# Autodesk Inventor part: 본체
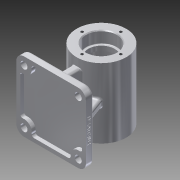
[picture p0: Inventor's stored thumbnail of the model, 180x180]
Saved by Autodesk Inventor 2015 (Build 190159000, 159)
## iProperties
Created: 2019-06
Part Number: 본체
Material: 알루미늄 6061
Document SubType Name: Modeling
Designer: a3
Density: 2.7 g/cm^3
Appearance: 알루미늄 - 평지
Mass: 610.032 g
Surface Area: 623.426 cm^2
Volume: 225.938 cm^3
Author: a3
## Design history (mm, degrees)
sketch "스케치2"
  geometry: L1 (45, 45)-(-45, 45); L2 (-45, 45)-(-45, -45); L3 (-45, -45)-(45, -45); L4 (45, -45)-(45, 45); L5 (45, 45)-(-45, -45); 2 further points
  constraints: 10 end point, 2 parallel, 1 coincident, 1 horizontal, 1 midpoint, 1 perpendicular
  dimensions: "d4" = 90 distance of L3.end L1.start; "d5" = 90 distance of L1.start L1.end
extrude "돌출2" new body sketch "스케치2" distance "d6" = 10; taper "d7" = 0 deg
sketch "스케치3"
  geometry: L1 (65, 40.611)-(65, -47.854); L2 (85, 45)-(85, 30); L3 (85, 30)-(82, 30); L4 (82, 30)-(82, 24); L5 (82, 24)-(90, 24); L6 (90, 24)-(90, -24); L7 (90, -24)-(82, -24); L8 (82, -24)-(82, -30); L9 (82, -30)-(85, -30); L10 (85, -30)-(85, -45); L11 (85, -45)-(97, -45); L12 (97, -45)-(97, 45); L13 (97, 45)-(85, 45); L14 (0, 45)-(0, -45) reference; 1 further point
  constraints: 26 end point, 10 perpendicular, 2 collinear, 2 vertical, 1 horizontal
  dimensions: "d8" = 65 distance between parallel lines of L1 L14; "d9" = 64 diameter of L12 L1; "d10" = 34 diameter of L4 L1; "d11" = 40 diameter of L2 L1; "d12" = 50 diameter of L6 L1; "d13" = 90 distance between parallel lines of L11 L13; "d14" = 45 distance from line of L11 point (0, 0); "d15" = 48 distance between parallel lines of L7 L5; "d16" = 15 distance from line of L3.end L13; "d17" = 15 distance from line of L11 L8.end; "d18" = 24 distance from line of L7 point (0, 0)
revolve "회전1" sketch "스케치3" stored, may be unused: angle "d19" = 90 deg
sketch "스케치4"
  geometry: L1 (-5, -35)-(5, -35); L2 (5, -35)-(5, 35); L3 (5, 35)-(-5, 35); L4 (-5, 35)-(-5, -35); L5 (-5, -35)-(5, 35); 2 further points
  constraints: 10 end point, 2 parallel, 1 coincident, 1 horizontal, 1 midpoint, 1 perpendicular
  dimensions: "d20" = 70 distance of L3.end L1.start; "d21" = 10 distance of L1.start L1.end
extrude "돌출3" join sketch "스케치4" stored distance "d22" = 10; taper "d23" = 0 deg
sketch "스케치5"
  geometry: L1 (0, 0)-(0, 40); L2 (-35, 10)-(-23.058, 42.811); 2 further points
  constraints: 4 end point, 1 vertical, 1 vertical alignment, 3 other
  dimensions: "d33" = 20 deg angle of L2 L1; "d34" = 14.07813 distance from line of point (0, 65) L2; "d35" = 35 distance from line of L2.start L1
feature "리브1" sketch "스케치5" dims "d27" = 1, "d28" = 10, "d29" = 0, "d30" = 0, "d31" = 1, "d32" = 1
fillet "모깎기1" dims "d40" = 10
sketch "스케치6"
  geometry: L1 (22.155, 40)-(-22.155, 40); L2 (-22.155, -40)-(22.155, -40); L3 (40, -22.155)-(40, 22.155); L4 (-40, -40)-(40, 40); L5 (-40, -22.155)-(-40, 22.155); A1 r 10 centre (-35, -35) between (-45, -35) and (-35, -45) reference; A2 r 10 centre (35, -35) between (35, -45) and (45, -35) reference; A3 r 10 centre (35, 35) between (45, 35) and (35, 45) reference; A4 r 10 centre (-35, 35) between (-35, 45) and (-45, 35) reference; A5 r 10 centre (-35, -35) between (-25.119, -36.538) and (-36.538, -25.119); A6 r 10 centre (-35, 35) between (-36.538, 25.119) and (-25.119, 36.538); A7 r 10 centre (35, 35) between (45, 35) and (35, 45) reference; A8 r 10 centre (35, 35) between (25.119, 36.538) and (36.538, 25.119); A9 r 10 centre (35, -35) between (36.538, -25.119) and (25.119, -36.538); A10 r 3 centre (-37, -22.155) between (-40, -22.155) and (-36.538, -25.119); A11 r 3 centre (-22.155, -37) between (-25.119, -36.538) and (-22.155, -40); A12 r 3 centre (22.155, -37) between (22.155, -40) and (25.119, -36.538); A13 r 3 centre (37, -22.155) between (36.538, -25.119) and (40, -22.155); A14 r 3 centre (37, 22.155) between (40, 22.155) and (36.538, 25.119); A15 r 3 centre (22.155, 37) between (25.119, 36.538) and (22.155, 40); A16 r 3 centre (-22.155, 37) between (-22.155, 40) and (-25.119, 36.538); A17 r 3 centre (-37, 22.155) between (-36.538, 25.119) and (-40, 22.155); 10 further points
  constraints: 32 point on circle, 16 tangent, 12 centre point, 10 end point, 8 point on line, 6 equal radius, 5 coincident, 2 parallel, 1 horizontal, 1 midpoint, 1 vertical
  dimensions: "d41" = 20 diameter of A8; "d42" = 20 diameter of A9; "d43" = 20 diameter of A6; "d44" = 20 diameter of A5; "d45" = 45 deg angle of L3 L4; "d47" = 80 distance between parallel lines of L1 L2; "d48" = 5 distance from line of A3.start L3; "d49" = 75 distance from line of A3.start L2; "d50" = 3 radius of A10; "d51" = 3 radius of A11; "d52" = 80 distance between parallel lines of L3 L5; "d53" = 0 distance from line of L4.end L3
extrude "돌출4" cut sketch "스케치6" distance "d54" = 5; taper "d55" = 0 deg
sketch "스케치7"
  geometry: L1 (35, 45)-(-35, 45) reference; L2 (-45, 35)-(-45, -35) reference; L3 (-35, -45)-(35, -45) reference; L4 (45, -35)-(45, 35) reference; L5 (-35, -5)-(-35, 5) reference; L6 (-35, 5)-(-5, 5) reference; L7 (-5, 5)-(-5, 35) reference; L8 (-5, 35)-(5, 35) reference; L9 (5, 35)-(5, 5) reference; L10 (5, 5)-(35, 5) reference; L11 (35, 5)-(35, -5) reference; L12 (35, -5)-(5, -5) reference; L13 (5, -5)-(5, -35) reference; L14 (5, -35)-(-5, -35) reference; L15 (-5, -35)-(-5, -5) reference; L16 (-5, -5)-(-35, -5) reference; A1 r 10 centre (35, 35) between (45, 35) and (35, 45) reference; A2 r 10 centre (-35, 35) between (-35, 45) and (-45, 35) reference; A3 r 10 centre (-35, -35) between (-45, -35) and (-35, -45) reference; A4 r 10 centre (35, -35) between (35, -45) and (45, -35) reference; 1 further point
hole "구멍1" sketch "스케치7" at (-35, 35), (-35, -35), (35, -35), (35, 35) diameter "d56" = 9; stored, may be unused: countersink angle "d60" = 90 deg, drill point angle "d62" = 118 deg; dims "d57" = 6, "d58" = 4, "d59" = 2, "d61" = 8
sketch "스케치8"
  geometry: L1 (0, 0)-(0, 25); C1 r 20 at (0, 0) reference; 1 further point
  constraints: 2 end point, 1 vertical
  dimensions: "d63" = 25 distance of L1.start L1.end
hole "구멍2" sketch "스케치8" at (0, 25) diameter "d64" = 3.459; stored, may be unused: countersink angle "d68" = 90 deg, drill point angle "d70" = 118 deg; dims "d65" = 7, "d66" = 4, "d67" = 2, "d69" = 9
node "작업 평면1"
sketch "스케치9"
  geometry: C1 r 5 at (0, 0); 1 further point
  constraints: 1 centre point, 1 coincident
  dimensions: "d76" = 10 diameter of C1
extrude "돌출5" join sketch "스케치9" stored distance "d77" = 5; taper "d78" = 0 deg
sketch "스케치10"
  geometry: C1 r 5 at (0, 0) reference; 1 further point
hole "구멍3" sketch "스케치10" at (0, 0) diameter "d79" = 4.917; stored, may be unused: countersink angle "d83" = 90 deg, drill point angle "d85" = 118 deg; dims "d80" = 12, "d81" = 4, "d82" = 2, "d84" = 17.1
fillet "모깎기2" dims "d86" = 3
fillet "모깎기3" dims "d87" = 3
fillet "모깎기4" dims "d88" = 2
fillet "모깎기5" dims "d89" = 0.6
fillet "모깎기7" dims "d91" = 0.6
chamfer "모따기1" distance "d92" = 1; stored, may be unused: second distance "d93" = 2, angle "d94" = 45 deg
sketch "스케치11"
  geometry: L1 (-10, 7)-(-10, 0) reference; L2 (0, 0)-(-10, 0) reference; 2 further points
  constraints: 1 other
  dimensions: "d95" = 45 distance from line of point (35, 4) L1; "d97" = 4 distance from line of point (35, 4) L2
feature "엠보싱1" sketch "스케치11" dims "d4" = 90, "d5" = 90, "d8" = 65, "d9" = 64, "d10" = 34, "d11" = 40, "d12" = 50, "d13" = 90, "d14" = 45, "d15" = 48, "d16" = 15, "d17" = 15, "d18" = 24, "d98" = 0.5, "d99" = 0
fillet "모깎기8" dims "d100" = 3
node "솔리드2"
mirror "대칭1"
pattern_circular "원형 패턴1" dims angle "d72" = 360 deg
mirror "대칭2"
node "투영된 루프1"
node "투영된 루프2"
other parameters: "d26" = 110 deg
